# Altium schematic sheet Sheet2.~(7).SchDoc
size A
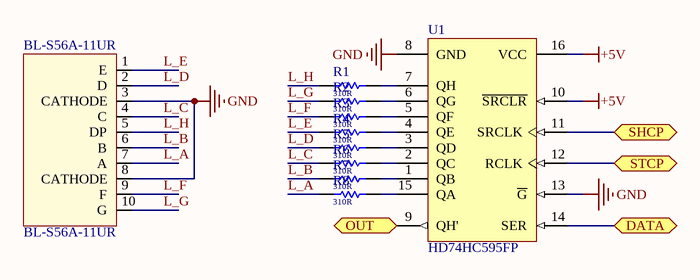
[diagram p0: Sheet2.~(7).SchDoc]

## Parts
BL-S56A-11UR  BL-S56A-11UR  [BL-S56A-11UR]
R1  310R  [3-0603]
R2  310R  [3-0603]
R3  310R  [3-0603]
R4  310R  [3-0603]
R5  310R  [3-0603]
R6  310R  [3-0603]
R7  310R  [3-0603]
R8  310R  [3-0603]
U1  HD74HC595FP  [PRSP0016DH-B_N]

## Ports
DATA, OUT (out), SHCP, STCP

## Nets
+5V: U1.10(~{SRCLR}) U1.16(VCC)
GND: BL-S56A-11UR.3(CATHODE) BL-S56A-11UR.8(CATHODE) U1.8(GND) U1.13(~{G})
DATA: U1.14(SER) ; port DATA
L_A: BL-S56A-11UR.7(A) R8.1
L_B: BL-S56A-11UR.6(B) R7.1
L_C: BL-S56A-11UR.4(C) R6.1
L_D: BL-S56A-11UR.2(D) R5.1
L_E: BL-S56A-11UR.1(E) R4.1
L_F: BL-S56A-11UR.9(F) R3.1
L_G: BL-S56A-11UR.10(G) R2.1
L_H: BL-S56A-11UR.5(DP) R1.1
OUT: U1.9(QH') ; port OUT
SHCP: U1.11(SRCLK) ; port SHCP
STCP: U1.12(RCLK) ; port STCP
NetR1_2: R1.2 U1.7(QH)
NetR2_2: R2.2 U1.6(QG)
NetR3_2: R3.2 U1.5(QF)
NetR4_2: R4.2 U1.4(QE)
NetR5_2: R5.2 U1.3(QD)
NetR6_2: R6.2 U1.2(QC)
NetR7_2: R7.2 U1.1(QB)
NetR8_2: R8.2 U1.15(QA)

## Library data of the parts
BL-S56A-11UR = Component_1
R1-R8 = Res1: Resistor
U1 = HD74HC595FP: 8-bit Shift Register / Latch with 3-State Outputs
